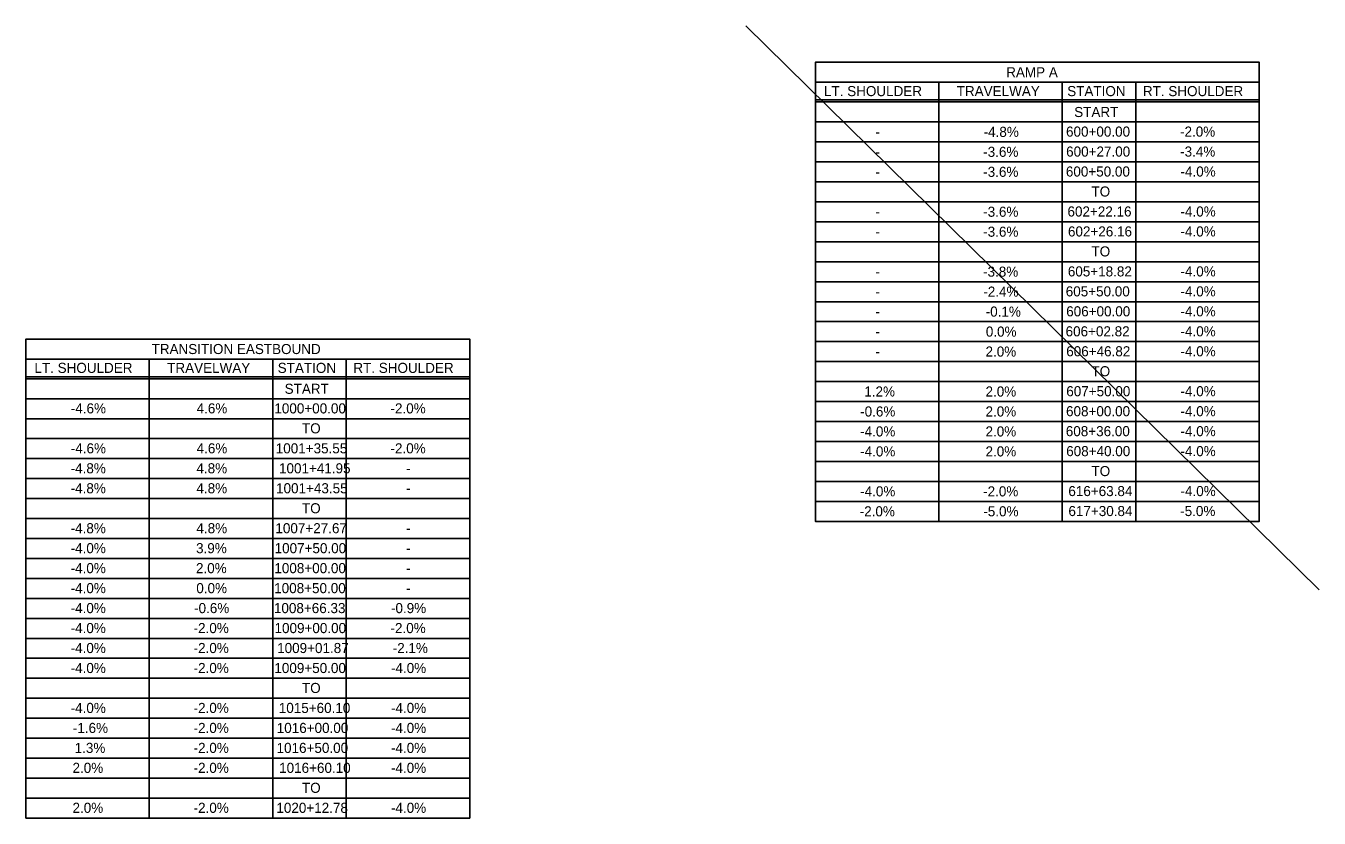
# Model space of a CAD drawing. Extents: x -15318841 to 1762012, y 465773 to 3693661.
# Drawn here: x -15317867.6 to -15317482.5, y 3691641.8 to 3691877.5 of the extents above; entities that cross this region are included whole.
import ezdxf

# ---------------------------------------------------------------- set-up
doc = ezdxf.new("R2010")
doc.units = 0
doc.layers.add('BORDER', color=7, linetype='Continuous')
doc.layers.add('DIMENSIONS', color=7, linetype='Continuous')

msp = doc.modelspace()

# ---------------------------------------------------------------- linework, layer by layer
at = {"layer": 'BORDER'}
for p, q in [((-15317653.2, 3691877.5), (-15317482.45, 3691709.72)), ((-15317632.48, 3691860.74), (-15317632.48, 3691742.54)), ((-15317595.71, 3691860.74), (-15317595.71, 3691730.07)), ((-15317558.94, 3691860.74), (-15317558.94, 3691730.07)), ((-15317537.07, 3691860.74), (-15317537.07, 3691730.07)), ((-15317500.3, 3691860.74), (-15317500.3, 3691730.07)), ((-15317632.48, 3691855.46), (-15317500.3, 3691855.46)), ((-15317632.48, 3691854.87), (-15317500.3, 3691854.87)), ((-15317632.48, 3691848.92), (-15317500.3, 3691848.92)), ((-15317632.48, 3691848.92), (-15317500.3, 3691848.92)), ((-15317632.48, 3691848.92), (-15317500.3, 3691848.92)), ((-15317632.48, 3691842.98), (-15317500.3, 3691842.98)), ((-15317632.48, 3691837.04), (-15317500.3, 3691837.04)), ((-15317632.48, 3691831.1), (-15317500.3, 3691831.1)), ((-15317632.48, 3691825.15), (-15317500.3, 3691825.15)), ((-15317632.48, 3691819.21), (-15317500.3, 3691819.21)), ((-15317632.48, 3691813.27), (-15317500.3, 3691813.27)), ((-15317632.48, 3691807.33), (-15317500.3, 3691807.33)), ((-15317632.48, 3691801.38), (-15317500.3, 3691801.38)), ((-15317632.48, 3691795.44), (-15317500.3, 3691795.44)), ((-15317632.48, 3691789.5), (-15317500.3, 3691789.5)), ((-15317632.48, 3691783.56), (-15317500.3, 3691783.56)), ((-15317867.63, 3691778.38), (-15317867.63, 3691660.18)), ((-15317830.87, 3691778.38), (-15317830.87, 3691641.76)), ((-15317794.1, 3691778.38), (-15317794.1, 3691641.76)), ((-15317772.22, 3691778.38), (-15317772.22, 3691641.76)), ((-15317632.48, 3691777.61), (-15317500.3, 3691777.61)), ((-15317867.63, 3691773.1), (-15317735.45, 3691773.1)), ((-15317867.63, 3691772.5), (-15317735.45, 3691772.5)), ((-15317632.48, 3691771.67), (-15317500.3, 3691771.67)), ((-15317867.63, 3691766.56), (-15317735.45, 3691766.56)), ((-15317867.63, 3691766.56), (-15317735.45, 3691766.56)), ((-15317867.63, 3691766.56), (-15317735.45, 3691766.56)), ((-15317632.48, 3691765.73), (-15317500.3, 3691765.73)), ((-15317867.63, 3691760.62), (-15317735.45, 3691760.62)), ((-15317632.48, 3691759.78), (-15317500.3, 3691759.78)), ((-15317867.63, 3691754.68), (-15317735.45, 3691754.68)), ((-15317632.48, 3691753.84), (-15317500.3, 3691753.84)), ((-15317867.63, 3691748.73), (-15317735.45, 3691748.73)), ((-15317632.48, 3691747.9), (-15317500.3, 3691747.9)), ((-15317867.63, 3691742.79), (-15317735.45, 3691742.79)), ((-15317632.48, 3691741.96), (-15317500.3, 3691741.96)), ((-15317867.63, 3691736.85), (-15317735.45, 3691736.85)), ((-15317632.48, 3691736.01), (-15317500.3, 3691736.01)), ((-15317867.63, 3691730.91), (-15317735.45, 3691730.91)), ((-15317867.63, 3691724.96), (-15317735.45, 3691724.96)), ((-15317867.63, 3691719.02), (-15317735.45, 3691719.02)), ((-15317867.63, 3691713.08), (-15317735.45, 3691713.08)), ((-15317867.63, 3691707.13), (-15317735.45, 3691707.13)), ((-15317867.63, 3691701.19), (-15317735.45, 3691701.19)), ((-15317867.63, 3691695.25), (-15317735.45, 3691695.25)), ((-15317867.63, 3691689.31), (-15317735.45, 3691689.31)), ((-15317867.63, 3691683.36), (-15317735.45, 3691683.36)), ((-15317867.63, 3691677.42), (-15317735.45, 3691677.42)), ((-15317867.63, 3691671.48), (-15317735.45, 3691671.48)), ((-15317867.63, 3691665.54), (-15317735.45, 3691665.54)), ((-15317867.63, 3691659.59), (-15317735.45, 3691659.59)), ((-15317867.63, 3691653.65), (-15317735.45, 3691653.65)), ((-15317867.63, 3691647.71), (-15317735.45, 3691647.71)), ((-15317867.63, 3691641.76), (-15317735.45, 3691641.76))]:
    msp.add_line(p, q, dxfattribs=at)
for points in [[(-15317632.48, 3691860.74), (-15317632.48, 3691866.69), (-15317500.3, 3691866.69), (-15317500.3, 3691860.74)], [(-15317867.63, 3691778.38), (-15317867.63, 3691784.32), (-15317735.45, 3691784.32), (-15317735.45, 3691778.38)]]:
    msp.add_lwpolyline(points, dxfattribs=at)
for points in [[(-15317632.48, 3691860.74), (-15317500.3, 3691860.74), (-15317500.3, 3691730.07), (-15317632.48, 3691730.07)], [(-15317867.63, 3691778.38), (-15317735.45, 3691778.38), (-15317735.45, 3691641.76), (-15317867.63, 3691641.76)]]:
    msp.add_lwpolyline(points, close=True, dxfattribs=at)

# ---------------------------------------------------------------- texts
at = {"layer": 'DIMENSIONS'}
for s, p in [('RAMP A', (-15317575.66, 3691862.22)), ('LT. SHOULDER', (-15317629.92, 3691856.6)), ('TRAVELWAY', (-15317590.39, 3691856.6)), ('STATION', (-15317557.48, 3691856.6)), ('RT. SHOULDER', (-15317534.94, 3691856.6)), ('START', (-15317555.4, 3691850.38)), ('-', (-15317614.6, 3691844.47)), ('-4.8%', (-15317582.38, 3691844.47)), ('600+00.00', (-15317557.83, 3691844.55)), ('-2.0%', (-15317523.88, 3691844.55)), ('-3.6%', (-15317582.5, 3691838.53)), ('600+27.00', (-15317557.8, 3691838.61)), ('-3.4%', (-15317523.85, 3691838.61)), ('-', (-15317614.6, 3691838.53)), ('-', (-15317614.6, 3691832.58)), ('-3.6%', (-15317582.5, 3691832.58)), ('600+50.00', (-15317557.88, 3691832.67)), ('-4.0%', (-15317523.74, 3691832.67)), ('TO', (-15317550.25, 3691826.72)), ('-3.6%', (-15317582.5, 3691820.7)), ('602+22.16', (-15317557.4, 3691820.78)), ('-4.0%', (-15317523.74, 3691820.78)), ('-', (-15317614.6, 3691820.7)), ('-', (-15317614.6, 3691814.76)), ('-3.6%', (-15317582.5, 3691814.76)), ('602+26.16', (-15317557.26, 3691814.84)), ('-4.0%', (-15317523.74, 3691814.84)), ('TO', (-15317550.25, 3691808.9)), ('-', (-15317614.6, 3691802.87)), ('-3.8%', (-15317582.54, 3691802.87)), ('605+18.82', (-15317557.3, 3691802.95)), ('-4.0%', (-15317523.74, 3691802.95)), ('-2.4%', (-15317582.47, 3691796.93)), ('605+50.00', (-15317557.92, 3691797.01)), ('-4.0%', (-15317523.74, 3691797.01)), ('-', (-15317614.6, 3691796.93)), ('-', (-15317614.6, 3691790.99)), ('-0.1%', (-15317581.76, 3691790.99)), ('606+00.00', (-15317557.78, 3691791.07)), ('-4.0%', (-15317523.74, 3691791.07)), ('0.0%', (-15317581.72, 3691785.04)), ('606+02.82', (-15317557.96, 3691785.12)), ('-4.0%', (-15317523.74, 3691785.12)), ('-', (-15317614.6, 3691785.04)), ('TRANSITION EASTBOUND', (-15317830.19, 3691779.85)), ('-', (-15317614.6, 3691779.1)), ('2.0%', (-15317581.81, 3691779.1)), ('606+46.82', (-15317557.77, 3691779.18)), ('-4.0%', (-15317523.74, 3691779.18)), ('LT. SHOULDER', (-15317865.08, 3691774.24)), ('TRAVELWAY', (-15317825.54, 3691774.24)), ('STATION', (-15317792.63, 3691774.24)), ('RT. SHOULDER', (-15317770.1, 3691774.24)), ('TO', (-15317550.25, 3691773.24)), ('START', (-15317790.56, 3691768.02)), ('1.2%', (-15317617.92, 3691767.21)), ('2.0%', (-15317581.81, 3691767.21)), ('607+50.00', (-15317557.76, 3691767.3)), ('-4.0%', (-15317523.74, 3691767.3)), ('-4.6%', (-15317854.25, 3691762.19)), ('4.6%', (-15317816.78, 3691762.19)), ('1000+00.00', (-15317793.62, 3691762.19)), ('-2.0%', (-15317759.03, 3691762.19)), ('-0.6%', (-15317619.15, 3691761.27)), ('2.0%', (-15317581.81, 3691761.27)), ('608+00.00', (-15317557.83, 3691761.35)), ('-4.0%', (-15317523.74, 3691761.35)), ('TO', (-15317785.4, 3691756.25)), ('-4.0%', (-15317619.15, 3691755.33)), ('2.0%', (-15317581.81, 3691755.33)), ('608+36.00', (-15317557.9, 3691755.41)), ('-4.0%', (-15317523.74, 3691755.41)), ('-4.6%', (-15317854.25, 3691750.3)), ('4.6%', (-15317816.78, 3691750.3)), ('1001+35.55', (-15317793.21, 3691750.3)), ('-2.0%', (-15317759.03, 3691750.3)), ('-4.0%', (-15317619.15, 3691749.39)), ('2.0%', (-15317581.81, 3691749.39)), ('608+40.00', (-15317557.78, 3691749.47)), ('-4.0%', (-15317523.74, 3691749.47)), ('-4.8%', (-15317854.3, 3691744.36)), ('4.8%', (-15317816.83, 3691744.36)), ('1001+41.95', (-15317792.24, 3691744.36)), ('-', (-15317754.35, 3691744.36)), ('TO', (-15317550.25, 3691743.53)), ('-4.8%', (-15317854.3, 3691738.42)), ('4.8%', (-15317816.83, 3691738.42)), ('1001+43.55', (-15317793.11, 3691738.42)), ('-', (-15317754.35, 3691738.42)), ('-4.0%', (-15317619.15, 3691737.5)), ('-2.0%', (-15317582.52, 3691737.5)), ('616+63.84', (-15317557.14, 3691737.58)), ('-4.0%', (-15317523.74, 3691737.58)), ('TO', (-15317785.4, 3691732.47)), ('-2.0%', (-15317619.29, 3691731.56)), ('-5.0%', (-15317582.47, 3691731.56)), ('617+30.84', (-15317557.12, 3691731.64)), ('-5.0%', (-15317523.83, 3691731.64)), ('-4.8%', (-15317854.3, 3691726.53)), ('4.8%', (-15317816.83, 3691726.53)), ('1007+27.67', (-15317793.31, 3691726.53)), ('-', (-15317754.35, 3691726.53)), ('-4.0%', (-15317854.3, 3691720.59)), ('3.9%', (-15317816.94, 3691720.59)), ('1007+50.00', (-15317793.55, 3691720.59)), ('-', (-15317754.35, 3691720.59)), ('-4.0%', (-15317854.3, 3691714.65)), ('2.0%', (-15317816.97, 3691714.65)), ('1008+00.00', (-15317793.62, 3691714.65)), ('-', (-15317754.35, 3691714.65)), ('-4.0%', (-15317854.3, 3691708.7)), ('0.0%', (-15317816.87, 3691708.7)), ('1008+50.00', (-15317793.67, 3691708.7)), ('-', (-15317754.35, 3691708.7)), ('-4.0%', (-15317854.3, 3691702.76)), ('-0.6%', (-15317817.53, 3691702.76)), ('1008+66.33', (-15317793.75, 3691702.76)), ('-0.9%', (-15317758.89, 3691702.76)), ('-4.0%', (-15317854.3, 3691696.82)), ('-2.0%', (-15317817.68, 3691696.82)), ('1009+00.00', (-15317793.57, 3691696.82)), ('-2.0%', (-15317759.03, 3691696.82)), ('-4.0%', (-15317854.3, 3691690.88)), ('-2.0%', (-15317817.68, 3691690.88)), ('1009+01.87', (-15317792.79, 3691690.88)), ('-2.1%', (-15317758.37, 3691690.88)), ('-4.0%', (-15317854.3, 3691684.93)), ('-2.0%', (-15317817.68, 3691684.93)), ('1009+50.00', (-15317793.62, 3691684.93)), ('-4.0%', (-15317758.89, 3691684.93)), ('TO', (-15317785.4, 3691678.99)), ('-4.0%', (-15317854.3, 3691673.05)), ('-2.0%', (-15317817.68, 3691673.05)), ('1015+60.10', (-15317792.3, 3691673.05)), ('-4.0%', (-15317758.89, 3691673.05)), ('-1.6%', (-15317853.64, 3691667.1)), ('-2.0%', (-15317817.68, 3691667.1)), ('1016+00.00', (-15317792.91, 3691667.1)), ('-4.0%', (-15317758.89, 3691667.1)), ('1.3%', (-15317853.1, 3691661.16)), ('-2.0%', (-15317817.68, 3691661.16)), ('1016+50.00', (-15317792.96, 3691661.16)), ('-4.0%', (-15317758.89, 3691661.16)), ('2.0%', (-15317853.74, 3691655.22)), ('-2.0%', (-15317817.68, 3691655.22)), ('1016+60.10', (-15317792.2, 3691655.22)), ('-4.0%', (-15317758.89, 3691655.22)), ('TO', (-15317785.4, 3691649.28)), ('2.0%', (-15317853.74, 3691643.33)), ('-2.0%', (-15317817.68, 3691643.33)), ('1020+12.78', (-15317793.02, 3691643.33)), ('-4.0%', (-15317758.89, 3691643.33))]:
    msp.add_text(s, height=3, dxfattribs=at).set_placement(p)

doc.saveas('drawing.dxf')
